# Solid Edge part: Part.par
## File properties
Author: CADCIM
Template: normal.par
Last saved by: CADCIM
Revision: 15
Application: Solid Edge
Accuracy: 0.99
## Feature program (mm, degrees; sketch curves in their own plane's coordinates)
sketch for "unnamed Protrusion 1" plane through (0, 0, 0) normal (0, 0, 1) x-axis (1, 0, 0)
  line (-63.0032, 49) -> (-56, -71)
  line (-56, -71) -> (56, -71)
  line (56, -71) -> (63.0032, 49)
  line (63.0032, 49) -> (0, 54)
  line (0, 54) -> (-63.0032, 49)
  dimension (linear) = 56
  dimension (linear) = 56
extrude "unnamed Protrusion 1" add finite 4 along +normal
fillet "Round_1" radius 15
sketch for "ExtrudedProtrusion_3" plane through (0, -8.5, 0) normal (0, 0, -1) x-axis (-1, 0, 0)
extrude "ExtrudedProtrusion_3" add finite 12 along -normal
pattern "unnamed Pattern 1" of "ExtrudedProtrusion_3"
pattern "unnamed Pattern 2"
sketch for "unnamed Protrusion 2" plane through (-1.0316, 2.3101, 4) normal (0, 0, 1) x-axis (-1, 0, 0)
extrude "unnamed Protrusion 2" add finite 5 along +normal
sketch for "Hole_22" plane through (40.9331, -54.9887, 12) normal (0, 0, 1) x-axis (1, 0, 0)
  hole centre (-0.4331, -0.0113) bore radius 4.5
hole "Hole_22" diameter 9 through  CounterBoreDepth = 5 mm
pattern "unnamed Pattern 3" of "Hole_22"
hole "unnamed Hole 1" through
hole "unnamed Hole 2" through
hole "unnamed Hole 3" through
sketch for "Hole_29" plane through (-1.0316, -6.1899, 9) normal (0, 0, 1) x-axis (1, 0, 0)
  hole centre (0, 0) bore radius 11
hole "Hole_29" diameter 22 through
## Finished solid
Body 1: solid body, 34 faces, 55 edges, 18 vertices.
  Faces by surface: cylinder 18, plane 16
  Edges by curve: circle 36, line 19
Bounding box of the edges (mm): 124.346 x 125.000 x 12.000, from (-62.1729, -71, 0) to (62.1729, 54, 12).
Cylindrical faces by radius (mm): R4.5 x4, R7.5 x4, R10.7006 x4, R11 x1, R15 x4, R20 x1
Planar faces by outward normal: +z 10, -y 1, -z 1, oblique 4
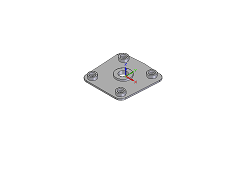
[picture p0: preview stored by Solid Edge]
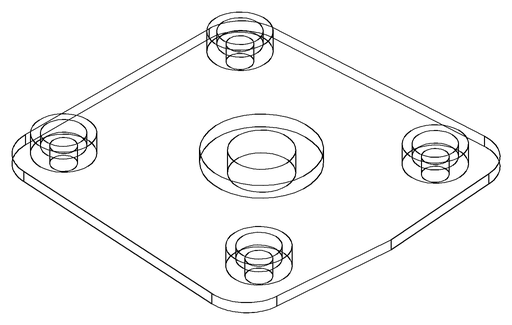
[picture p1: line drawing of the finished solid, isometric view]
